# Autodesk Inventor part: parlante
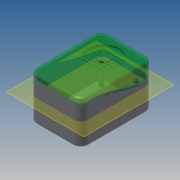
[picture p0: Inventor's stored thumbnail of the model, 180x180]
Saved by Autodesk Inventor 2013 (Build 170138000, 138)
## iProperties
Created: 2013-06
Part Number: parlante
Material: Generic
Document SubType Name: Modeling
Designer: julian.chica
Density: 1 g/cm^3
Author: julian.chica
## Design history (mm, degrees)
sketch "Sketch1"
  geometry: L1 (-6.795, 7.881)-(6.845, 7.881); L2 (6.845, 7.881)-(6.845, -11.064); L3 (6.845, -11.064)-(-6.795, -11.064); L4 (-6.795, -11.064)-(-6.795, 7.881); 1 further point
  constraints: 8 end point, 2 parallel, 1 horizontal, 1 perpendicular
extrude "Extrusion1" new body sketch "Sketch1" distance "d0" = 3; taper "d2" = 0 deg; dims "d1" = 8.25, "d3" = 0
fillet "Fillet1" dims "d4" = 2
fillet "Fillet2" dims "d5" = 0.5
sketch "Sketch2"
  geometry: 5 further points
  constraints: 4 other
extrude_surface "ExtrusionSrf1" sketch "Sketch2" dims "d6" = 18.5, "d7" = 0
shell "Shell1" dims "d8" = 0.5
split "Split1"
  body "Solid1"
sketch "Sketch3" dims "d14" = 10, "d21" = 10
  geometry: L1 (-5.349, 1.84)-(4.811, 1.84); L2 (-6.295, 5.881)-(-6.295, -9.064) reference; L3 (-5.349, 2.84)-(4.811, 2.84); L4 (-5.349, 3.84)-(4.811, 3.84); L5 (-5.349, 4.84)-(4.811, 4.84); L6 (-5.349, 0.84)-(4.811, 0.84); L7 (-5.349, -0.16)-(4.811, -0.16); L8 (-5.349, -1.16)-(4.811, -1.16); C1 r 3.995 at (0, 1.84); C2 r 1.512 at (0, 1.84); 1 further point
  constraints: 14 end point, 2 centre point, 2 vertical, 1 coincident, 1 horizontal, 18 other
  dimensions: "d11" = 1 distance of L1.start L3.start; "d18" = 1 distance of L1.start L6.start
feature "Grill1" sketch "Sketch3" dims "d24" = 0.4, "d25" = 0.1, "d26" = 0.2, "d27" = 0.2, "d28" = 0.1, "d29" = 0.3, "d30" = 0, "d31" = 0, "d32" = 1, "d33" = 0, "d34" = 0.12217, "d35" = 0, "d36" = 3.08699
feature "Lip1" dims "d37" = 0.3, "d38" = 0.2, "d39" = 0, "d40" = 0, "d41" = 0, "d42" = 0
workplane "Work Plane1"
sketch "Sketch4"
  geometry: 5 further points
feature "Boss1" sketch "Sketch4" dims "d44" = 0.1, "d45" = 0, "d46" = 0.7, "d47" = 0.2, "d48" = 0.5, "d49" = 0.4, "d50" = 1.25, "d51" = 0.001, "d52" = 1 deg, "d53" = 1 deg, "d54" = 1 deg, "d55" = 1 deg, "d56" = 90 deg, "d59" = 2, "d60" = 2, "d61" = 10, "d62" = 0, "d63" = 10 deg, "d64" = 2.5 deg, "d65" = 0, "d66" = 0, "d67" = 0, "d68" = 360 deg
body "Srf1"
body "Solid2"
body "Solid3"
other parameters: "d23" = 0.3, "d43" = -2.25
